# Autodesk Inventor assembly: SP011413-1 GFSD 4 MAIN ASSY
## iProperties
Created: 2013-01
Part Number: SP011413-1 GFSD 4 MAIN ASSY
Document SubType Name: Assembly
Designer: Administrator
Author: Administrator
